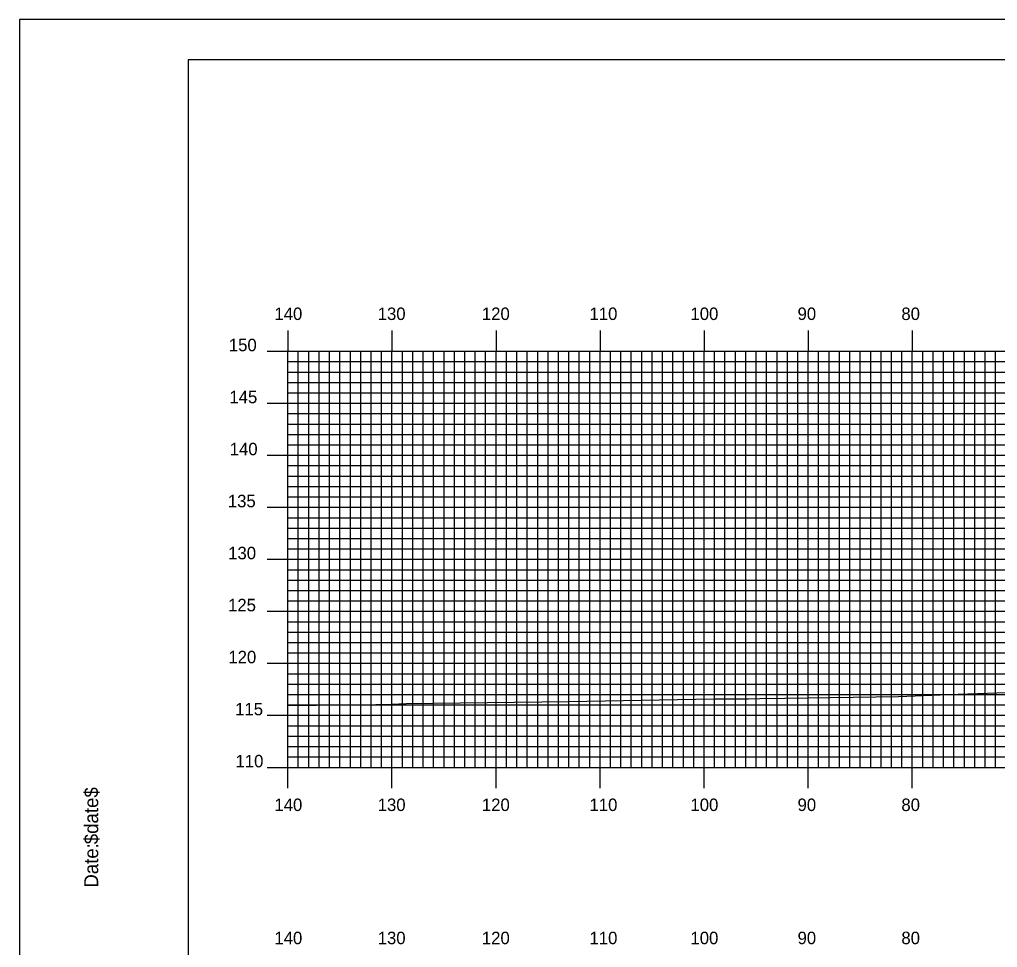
# Model space of a CAD drawing. Extents: x 1790124 to 1790467, y 442591 to 442811.
# Drawn here: x 1790123.9 to 1790217.9, y 442721.4 to 442810.5 of the extents above; entities that cross this region are included whole.
import ezdxf

# ---------------------------------------------------------------- set-up
doc = ezdxf.new("R2010")
doc.units = 0
for name, color, linetype in [('BORDER', 7, 'Continuous'), ('H_V ANNOTATION', 7, 'Continuous'), ('MAJOR', 7, 'Continuous'), ('MINOR', 7, 'Continuous'), ('PLOT BOUNDARY', 7, 'Continuous'), ('S_Roadway_Centerline', 7, 'Continuous')]:
    doc.layers.add(name, color=color, linetype=linetype)

msp = doc.modelspace()

# ---------------------------------------------------------------- linework, layer by layer
at = {"layer": 'BORDER'}
msp.add_lwpolyline([(1790140.096, 442596.665), (1790460.096, 442596.665), (1790460.096, 442806.665), (1790140.096, 442806.665)], close=True, dxfattribs=at)
at = {"layer": 'MAJOR'}
for p, q in [((1790149.696, 442780.669), (1790149.696, 442778.665)), ((1790159.696, 442780.669), (1790159.696, 442778.665)), ((1790169.696, 442780.669), (1790169.696, 442778.665)), ((1790179.696, 442780.669), (1790179.696, 442778.665)), ((1790189.696, 442780.669), (1790189.696, 442778.665)), ((1790199.696, 442780.669), (1790199.696, 442778.665)), ((1790209.696, 442780.669), (1790209.696, 442778.665)), ((1790147.692, 442778.665), (1790149.696, 442778.665)), ((1790149.696, 442778.665), (1790429.696, 442778.665)), ((1790149.696, 442738.665), (1790149.696, 442778.665)), ((1790149.696, 442738.665), (1790149.696, 442778.665)), ((1790149.696, 442778.665), (1790429.696, 442778.665)), ((1790159.696, 442738.665), (1790159.696, 442778.665)), ((1790169.696, 442738.665), (1790169.696, 442778.665)), ((1790179.696, 442738.665), (1790179.696, 442778.665)), ((1790189.696, 442738.665), (1790189.696, 442778.665)), ((1790199.696, 442738.665), (1790199.696, 442778.665)), ((1790209.696, 442738.665), (1790209.696, 442778.665)), ((1790147.692, 442773.665), (1790149.696, 442773.665)), ((1790149.696, 442773.665), (1790429.696, 442773.665)), ((1790147.692, 442768.665), (1790149.696, 442768.665)), ((1790149.696, 442768.665), (1790429.696, 442768.665)), ((1790147.692, 442763.665), (1790149.696, 442763.665)), ((1790149.696, 442763.665), (1790429.696, 442763.665)), ((1790147.692, 442758.665), (1790149.696, 442758.665)), ((1790149.696, 442758.665), (1790429.696, 442758.665)), ((1790147.692, 442753.665), (1790149.696, 442753.665)), ((1790149.696, 442753.665), (1790429.696, 442753.665)), ((1790147.692, 442748.665), (1790149.696, 442748.665)), ((1790149.696, 442748.665), (1790429.696, 442748.665)), ((1790147.692, 442743.665), (1790149.696, 442743.665)), ((1790149.696, 442743.665), (1790429.696, 442743.665)), ((1790147.692, 442738.665), (1790149.696, 442738.665)), ((1790149.696, 442738.665), (1790429.696, 442738.665)), ((1790149.696, 442738.665), (1790429.696, 442738.665)), ((1790149.696, 442736.661), (1790149.696, 442738.665)), ((1790159.696, 442736.661), (1790159.696, 442738.665)), ((1790169.696, 442736.661), (1790169.696, 442738.665)), ((1790179.696, 442736.661), (1790179.696, 442738.665)), ((1790189.696, 442736.661), (1790189.696, 442738.665)), ((1790199.696, 442736.661), (1790199.696, 442738.665)), ((1790209.696, 442736.661), (1790209.696, 442738.665))]:
    msp.add_line(p, q, dxfattribs=at)
at = {"layer": 'MINOR'}
for p, q in [((1790150.696, 442738.665), (1790150.696, 442778.665)), ((1790151.696, 442738.665), (1790151.696, 442778.665)), ((1790152.696, 442738.665), (1790152.696, 442778.665)), ((1790153.696, 442738.665), (1790153.696, 442778.665)), ((1790154.696, 442738.665), (1790154.696, 442778.665)), ((1790155.696, 442738.665), (1790155.696, 442778.665)), ((1790156.696, 442738.665), (1790156.696, 442778.665)), ((1790157.696, 442738.665), (1790157.696, 442778.665)), ((1790158.696, 442738.665), (1790158.696, 442778.665)), ((1790160.696, 442738.665), (1790160.696, 442778.665)), ((1790161.696, 442738.665), (1790161.696, 442778.665)), ((1790162.696, 442738.665), (1790162.696, 442778.665)), ((1790163.696, 442738.665), (1790163.696, 442778.665)), ((1790164.696, 442738.665), (1790164.696, 442778.665)), ((1790165.696, 442738.665), (1790165.696, 442778.665)), ((1790166.696, 442738.665), (1790166.696, 442778.665)), ((1790167.696, 442738.665), (1790167.696, 442778.665)), ((1790168.696, 442738.665), (1790168.696, 442778.665)), ((1790170.696, 442738.665), (1790170.696, 442778.665)), ((1790171.696, 442738.665), (1790171.696, 442778.665)), ((1790172.696, 442738.665), (1790172.696, 442778.665)), ((1790173.696, 442738.665), (1790173.696, 442778.665)), ((1790174.696, 442738.665), (1790174.696, 442778.665)), ((1790175.696, 442738.665), (1790175.696, 442778.665)), ((1790176.696, 442738.665), (1790176.696, 442778.665)), ((1790177.696, 442738.665), (1790177.696, 442778.665)), ((1790178.696, 442738.665), (1790178.696, 442778.665)), ((1790180.696, 442738.665), (1790180.696, 442778.665)), ((1790181.696, 442738.665), (1790181.696, 442778.665)), ((1790182.696, 442738.665), (1790182.696, 442778.665)), ((1790183.696, 442738.665), (1790183.696, 442778.665)), ((1790184.696, 442738.665), (1790184.696, 442778.665)), ((1790185.696, 442738.665), (1790185.696, 442778.665)), ((1790186.696, 442738.665), (1790186.696, 442778.665)), ((1790187.696, 442738.665), (1790187.696, 442778.665)), ((1790188.696, 442738.665), (1790188.696, 442778.665)), ((1790190.696, 442738.665), (1790190.696, 442778.665)), ((1790191.696, 442738.665), (1790191.696, 442778.665)), ((1790192.696, 442738.665), (1790192.696, 442778.665)), ((1790193.696, 442738.665), (1790193.696, 442778.665)), ((1790194.696, 442738.665), (1790194.696, 442778.665)), ((1790195.696, 442738.665), (1790195.696, 442778.665)), ((1790196.696, 442738.665), (1790196.696, 442778.665)), ((1790197.696, 442738.665), (1790197.696, 442778.665)), ((1790198.696, 442738.665), (1790198.696, 442778.665)), ((1790200.696, 442738.665), (1790200.696, 442778.665)), ((1790201.696, 442738.665), (1790201.696, 442778.665)), ((1790202.696, 442738.665), (1790202.696, 442778.665)), ((1790203.696, 442738.665), (1790203.696, 442778.665)), ((1790204.696, 442738.665), (1790204.696, 442778.665)), ((1790205.696, 442738.665), (1790205.696, 442778.665)), ((1790206.696, 442738.665), (1790206.696, 442778.665)), ((1790207.696, 442738.665), (1790207.696, 442778.665)), ((1790208.696, 442738.665), (1790208.696, 442778.665)), ((1790210.696, 442738.665), (1790210.696, 442778.665)), ((1790211.696, 442738.665), (1790211.696, 442778.665)), ((1790212.696, 442738.665), (1790212.696, 442778.665)), ((1790213.696, 442738.665), (1790213.696, 442778.665)), ((1790214.696, 442738.665), (1790214.696, 442778.665)), ((1790215.696, 442738.665), (1790215.696, 442778.665)), ((1790216.696, 442738.665), (1790216.696, 442778.665)), ((1790217.696, 442738.665), (1790217.696, 442778.665)), ((1790149.696, 442777.665), (1790429.696, 442777.665)), ((1790149.696, 442777.665), (1790151.7, 442777.665)), ((1790149.696, 442776.665), (1790429.696, 442776.665)), ((1790149.696, 442776.665), (1790151.7, 442776.665)), ((1790149.696, 442775.665), (1790429.696, 442775.665)), ((1790149.696, 442775.665), (1790151.7, 442775.665)), ((1790149.696, 442774.665), (1790429.696, 442774.665)), ((1790149.696, 442774.665), (1790151.7, 442774.665)), ((1790149.696, 442772.665), (1790429.696, 442772.665)), ((1790149.696, 442772.665), (1790151.7, 442772.665)), ((1790149.696, 442771.665), (1790429.696, 442771.665)), ((1790149.696, 442771.665), (1790151.7, 442771.665)), ((1790149.696, 442770.665), (1790429.696, 442770.665)), ((1790149.696, 442770.665), (1790151.7, 442770.665)), ((1790149.696, 442769.665), (1790429.696, 442769.665)), ((1790149.696, 442769.665), (1790151.7, 442769.665)), ((1790149.696, 442767.665), (1790429.696, 442767.665)), ((1790149.696, 442767.665), (1790151.7, 442767.665)), ((1790149.696, 442766.665), (1790429.696, 442766.665)), ((1790149.696, 442766.665), (1790151.7, 442766.665)), ((1790149.696, 442765.665), (1790429.696, 442765.665)), ((1790149.696, 442765.665), (1790151.7, 442765.665)), ((1790149.696, 442764.665), (1790429.696, 442764.665)), ((1790149.696, 442764.665), (1790151.7, 442764.665)), ((1790149.696, 442762.665), (1790429.696, 442762.665)), ((1790149.696, 442762.665), (1790151.7, 442762.665)), ((1790149.696, 442761.665), (1790429.696, 442761.665)), ((1790149.696, 442761.665), (1790151.7, 442761.665)), ((1790149.696, 442760.665), (1790429.696, 442760.665)), ((1790149.696, 442760.665), (1790151.7, 442760.665)), ((1790149.696, 442759.665), (1790429.696, 442759.665)), ((1790149.696, 442759.665), (1790151.7, 442759.665)), ((1790149.696, 442757.665), (1790429.696, 442757.665)), ((1790149.696, 442757.665), (1790151.7, 442757.665)), ((1790149.696, 442756.665), (1790429.696, 442756.665)), ((1790149.696, 442756.665), (1790151.7, 442756.665)), ((1790149.696, 442755.665), (1790429.696, 442755.665)), ((1790149.696, 442755.665), (1790151.7, 442755.665)), ((1790149.696, 442754.665), (1790429.696, 442754.665)), ((1790149.696, 442754.665), (1790151.7, 442754.665)), ((1790149.696, 442752.665), (1790429.696, 442752.665)), ((1790149.696, 442752.665), (1790151.7, 442752.665)), ((1790149.696, 442751.665), (1790429.696, 442751.665)), ((1790149.696, 442751.665), (1790151.7, 442751.665)), ((1790149.696, 442750.665), (1790429.696, 442750.665)), ((1790149.696, 442750.665), (1790151.7, 442750.665)), ((1790149.696, 442749.665), (1790429.696, 442749.665)), ((1790149.696, 442749.665), (1790151.7, 442749.665)), ((1790149.696, 442747.665), (1790429.696, 442747.665)), ((1790149.696, 442747.665), (1790151.7, 442747.665)), ((1790149.696, 442746.665), (1790429.696, 442746.665)), ((1790149.696, 442746.665), (1790151.7, 442746.665)), ((1790149.696, 442745.665), (1790429.696, 442745.665)), ((1790149.696, 442745.665), (1790151.7, 442745.665)), ((1790149.696, 442744.665), (1790429.696, 442744.665)), ((1790149.696, 442744.665), (1790151.7, 442744.665)), ((1790149.696, 442742.665), (1790429.696, 442742.665)), ((1790149.696, 442742.665), (1790151.7, 442742.665)), ((1790149.696, 442741.665), (1790429.696, 442741.665)), ((1790149.696, 442741.665), (1790151.7, 442741.665)), ((1790149.696, 442740.665), (1790429.696, 442740.665)), ((1790149.696, 442740.665), (1790151.7, 442740.665)), ((1790149.696, 442739.665), (1790429.696, 442739.665)), ((1790149.696, 442739.665), (1790151.7, 442739.665))]:
    msp.add_line(p, q, dxfattribs=at)
at = {"layer": 'PLOT BOUNDARY'}
msp.add_lwpolyline([(1790123.909, 442590.547), (1790463.909, 442590.547), (1790463.909, 442810.547), (1790123.909, 442810.547)], close=True, dxfattribs=at)
at = {"layer": 'S_Roadway_Centerline'}
msp.add_lwpolyline([(1790149.696, 442744.606), (1790155.234, 442744.687), (1790158.138, 442744.716), (1790158.916, 442744.71), (1790161.061, 442744.788), (1790176.695, 442745.002), (1790190.623, 442745.239), (1790193.97, 442745.243), (1790195.059, 442745.297), (1790197.439, 442745.325), (1790208.38, 442745.463), (1790213.163, 442745.664), (1790236.464, 442746.473)], dxfattribs=at)

# ---------------------------------------------------------------- texts
at = {"layer": 'BORDER'}
for s, p in [('$date$', (1790131.466, 442731.275)), ('Date:', (1790131.466, 442727.099))]:
    msp.add_text(s, height=1.3392, rotation=90, dxfattribs=at).set_placement(p)
at = {"layer": 'H_V ANNOTATION'}
for s, p in [('140', (1790148.401, 442781.665)), ('130', (1790158.326, 442781.665)), ('120', (1790168.336, 442781.665)), ('110', (1790178.679, 442781.665)), ('100', (1790188.379, 442781.665)), ('90', (1790198.668, 442781.665)), ('80', (1790208.647, 442781.665)), ('150', (1790144.02, 442778.665)), ('145', (1790144.073, 442773.665)), ('140', (1790144.106, 442768.665)), ('135', (1790143.924, 442763.665)), ('130', (1790143.956, 442758.665)), ('125', (1790143.945, 442753.665)), ('120', (1790143.977, 442748.665)), ('115', (1790144.63, 442743.665)), ('110', (1790144.662, 442738.665)), ('140', (1790148.401, 442734.465)), ('130', (1790158.326, 442734.465)), ('120', (1790168.336, 442734.465)), ('110', (1790178.679, 442734.465)), ('100', (1790188.379, 442734.465)), ('90', (1790198.668, 442734.465)), ('80', (1790208.647, 442734.465)), ('140', (1790148.401, 442721.665)), ('130', (1790158.326, 442721.665)), ('120', (1790168.336, 442721.665)), ('110', (1790178.679, 442721.665)), ('100', (1790188.379, 442721.665)), ('90', (1790198.668, 442721.665)), ('80', (1790208.647, 442721.665))]:
    msp.add_text(s, height=1.2, dxfattribs=at).set_placement(p)
at = {"layer": 'MAJOR'}
msp.add_text('-', height=0.012, dxfattribs=at).set_placement((1790149.687, 442738.665))

doc.saveas('drawing.dxf')
